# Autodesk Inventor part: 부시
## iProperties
Company: 한국ATC센터
Created: 2014-08
Part Number: 부시
Document SubType Name: Modeling
Designer: KYOUNG IL JANG
Density: 7.86 g/cm^3
Checked By: KYOUNG IL JANG
Material: 강, 연강
Mass: 50.2336 g
Surface Area: 30.183 cm^2
Volume: 6.39105 cm^3
Author: KYOUNG IL JANG
